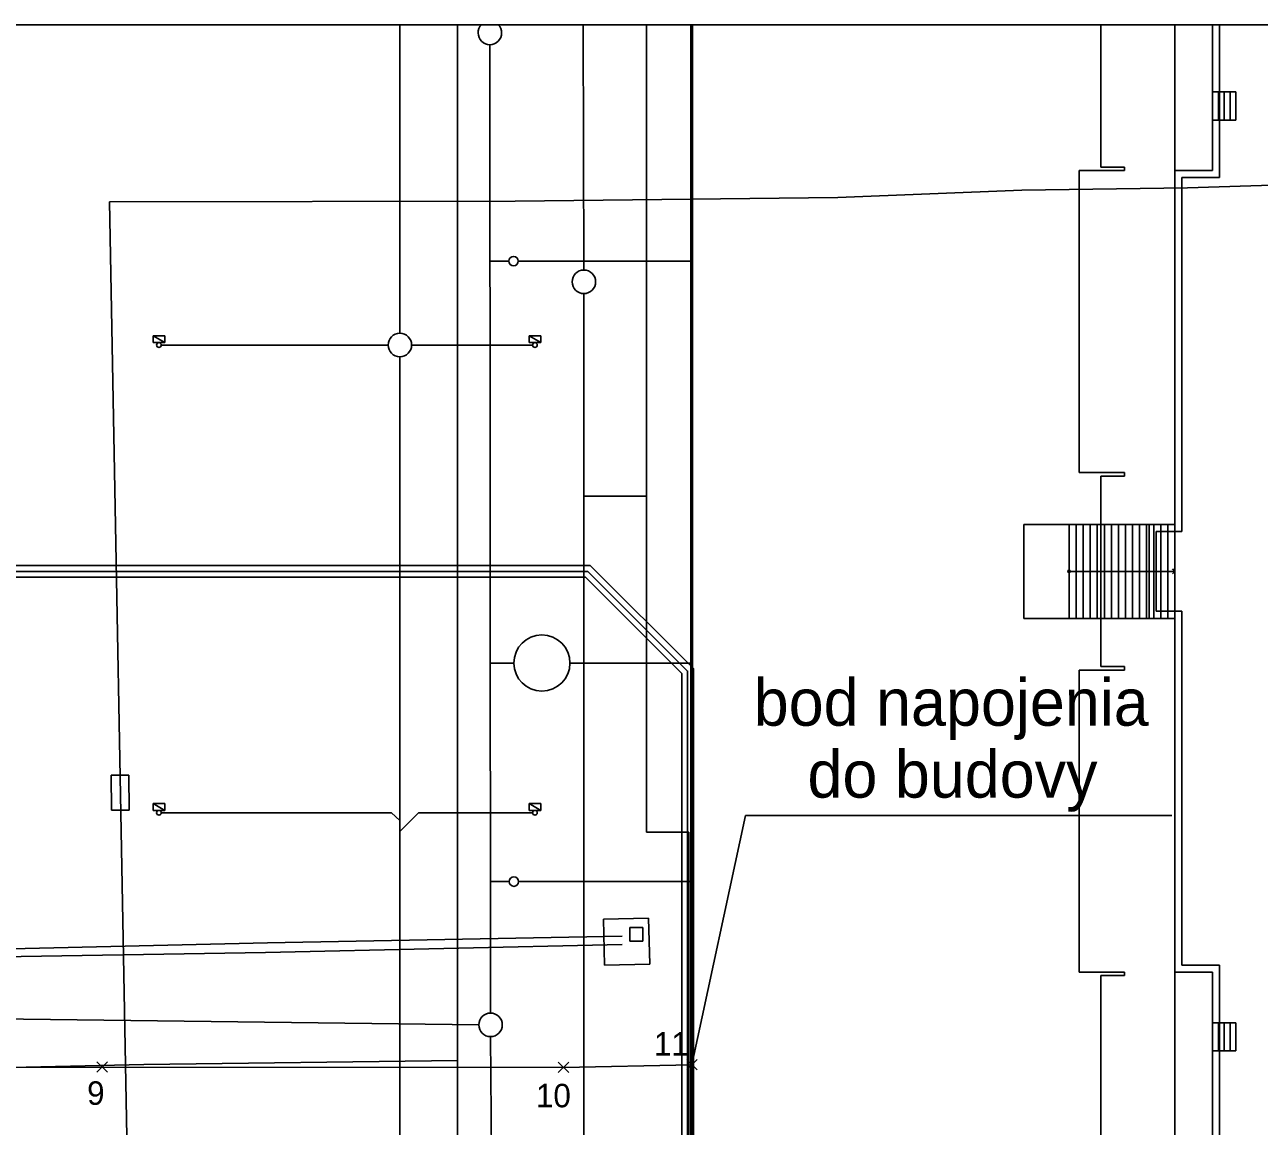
# Model space of a CAD drawing. Extents: x -264053 to -263843, y -1242290 to -1242141.
# Drawn here: x -263942.6 to -263890, y -1242188 to -1242141.1 of the extents above; entities that cross this region are included whole.
import ezdxf

# ---------------------------------------------------------------- set-up
doc = ezdxf.new("R2010")
doc.units = 0
for name, color, linetype in [('KFA_2D_JESTVUJUCE_IS_DSP', 7, 'Continuous'), ('KFA_2D_SITUACIA_DSP', 7, 'Continuous'), ('KFA_63-2_TELEKOM_PRIPOJKA', 7, 'Continuous'), ('KFA_BODY_CISLO', 7, 'Continuous'), ('KFA_BODY_SYMBOL', 7, 'Continuous'), ('POPIS', 7, 'Continuous'), ('RAM_NA_TLAC_A3_1-500', 7, 'Continuous')]:
    doc.layers.add(name, color=color, linetype=linetype)

msp = doc.modelspace()

# ---------------------------------------------------------------- linework, layer by layer
at = {"layer": 'KFA_2D_JESTVUJUCE_IS_DSP'}
for p, q in [((-263922.406, -1242141.125), (-263923.121, -1242141.125)), ((-263918.787, -1242141.125), (-263918.765, -1242151.564)), ((-263922.763, -1242141.975), (-263922.734, -1242183.174)), ((-263893.085, -1242148.072), (-263889.033, -1242147.931)), ((-263921.69, -1242148.626), (-263907.955, -1242148.477)), ((-263907.955, -1242148.477), (-263900.133, -1242148.17)), ((-263900.133, -1242148.17), (-263893.085, -1242148.072)), ((-263938.95, -1242148.666), (-263921.69, -1242148.626)), ((-263937.993, -1242200.068), (-263938.95, -1242148.666)), ((-263918.764, -1242152.564), (-263918.757, -1242196.225)), ((-263938.869, -1242173.048), (-263938.119, -1242173.046)), ((-263938.863, -1242174.548), (-263938.869, -1242173.048)), ((-263938.119, -1242173.046), (-263938.113, -1242174.546)), ((-263938.113, -1242174.546), (-263938.863, -1242174.548)), ((-263938.863, -1242174.548), (-263938.863, -1242174.548)), ((-263916.007, -1242179.139), (-263917.932, -1242179.184)), ((-263917.932, -1242179.184), (-263917.886, -1242181.133)), ((-263916.803, -1242180.116), (-263916.803, -1242179.537)), ((-263916.803, -1242179.537), (-263916.252, -1242179.537)), ((-263916.252, -1242179.537), (-263916.252, -1242180.116)), ((-263915.961, -1242181.088), (-263916.007, -1242179.139)), ((-263917.138, -1242179.908), (-263932.226, -1242180.187)), ((-263943.779, -1242180.456), (-263932.226, -1242180.187)), ((-263943.567, -1242180.776), (-263932.313, -1242180.597)), ((-263932.313, -1242180.597), (-263917.138, -1242180.263)), ((-263916.252, -1242180.116), (-263916.803, -1242180.116)), ((-263917.886, -1242181.133), (-263915.961, -1242181.088)), ((-263923.234, -1242183.668), (-263965.273, -1242183.165)), ((-263922.496, -1242219.209), (-263922.731, -1242184.174)), ((-263937.488, -1242185.363), (-263924.143, -1242185.192)), ((-263952.832, -1242185.692), (-263937.488, -1242185.363))]:
    msp.add_line(p, q, dxfattribs=at)
for centre in [(-263918.764, -1242152.064), (-263922.734, -1242183.674)]:
    msp.add_circle(centre, 0.5, dxfattribs=at)
msp.add_arc((-263922.763, -1242141.475), 0.5, 135.6071, 44.3929, dxfattribs=at)
at = {"layer": 'KFA_2D_SITUACIA_DSP'}
for p, q in [((-263926.593, -1242141.125), (-263926.593, -1242154.252)), ((-263926.593, -1242141.125), (-263926.593, -1242154.252)), ((-263924.143, -1242141.125), (-263924.143, -1242185.14)), ((-263893.618, -1242141.125), (-263916.093, -1242141.125)), ((-263916.093, -1242141.125), (-263916.093, -1242175.482)), ((-263914.218, -1242196.332), (-263914.218, -1242141.125)), ((-263896.768, -1242141.125), (-263896.768, -1242147.182)), ((-263893.618, -1242162.382), (-263893.618, -1242141.125)), ((-263843.272, -1242141.125), (-263892.018, -1242141.125)), ((-263892.018, -1242141.125), (-263892.018, -1242147.332)), ((-263892.018, -1242147.332), (-263892.018, -1242141.125)), ((-263892.018, -1242141.125), (-263843.272, -1242141.125)), ((-263843.272, -1242141.125), (-263891.718, -1242141.125)), ((-263891.718, -1242141.125), (-263891.718, -1242147.632)), ((-263892.018, -1242143.983), (-263891.018, -1242143.983)), ((-263891.768, -1242143.983), (-263891.768, -1242145.181)), ((-263891.518, -1242143.983), (-263891.518, -1242145.181)), ((-263891.268, -1242143.983), (-263891.268, -1242145.181)), ((-263891.018, -1242143.983), (-263891.018, -1242145.181)), ((-263891.018, -1242145.181), (-263892.018, -1242145.181)), ((-263895.768, -1242147.332), (-263897.693, -1242147.332)), ((-263897.693, -1242147.332), (-263897.693, -1242160.182)), ((-263896.768, -1242147.182), (-263895.768, -1242147.182)), ((-263895.768, -1242147.182), (-263895.768, -1242147.332)), ((-263892.018, -1242147.332), (-263893.618, -1242147.332)), ((-263893.618, -1242147.332), (-263893.618, -1242162.382)), ((-263893.618, -1242181.432), (-263893.618, -1242147.332)), ((-263893.618, -1242147.332), (-263892.018, -1242147.332)), ((-263891.718, -1242147.632), (-263893.318, -1242147.632)), ((-263893.318, -1242147.632), (-263893.318, -1242162.682)), ((-263921.957, -1242151.182), (-263922.757, -1242151.182)), ((-263917.093, -1242151.182), (-263921.557, -1242151.182)), ((-263914.143, -1242151.182), (-263917.093, -1242151.182)), ((-263937.093, -1242154.652), (-263937.093, -1242154.362)), ((-263937.093, -1242154.362), (-263936.593, -1242154.362)), ((-263936.593, -1242154.652), (-263937.093, -1242154.362)), ((-263936.593, -1242154.652), (-263937.093, -1242154.362)), ((-263937.093, -1242154.362), (-263937.093, -1242154.652)), ((-263936.593, -1242154.652), (-263937.093, -1242154.652)), ((-263937.093, -1242154.652), (-263936.593, -1242154.652)), ((-263936.743, -1242154.752), (-263927.093, -1242154.752)), ((-263936.593, -1242154.362), (-263936.593, -1242154.652)), ((-263920.944, -1242154.752), (-263926.093, -1242154.752)), ((-263921.093, -1242154.652), (-263921.093, -1242154.362)), ((-263921.093, -1242154.362), (-263920.593, -1242154.362)), ((-263920.593, -1242154.652), (-263921.093, -1242154.362)), ((-263920.593, -1242154.652), (-263921.093, -1242154.362)), ((-263921.093, -1242154.362), (-263921.093, -1242154.652)), ((-263920.593, -1242154.652), (-263921.093, -1242154.652)), ((-263921.093, -1242154.652), (-263920.593, -1242154.652)), ((-263920.593, -1242154.362), (-263920.593, -1242154.652)), ((-263926.593, -1242155.252), (-263926.593, -1242204.252)), ((-263897.693, -1242160.182), (-263895.768, -1242160.182)), ((-263895.768, -1242160.332), (-263896.768, -1242160.332)), ((-263896.768, -1242160.332), (-263896.768, -1242168.432)), ((-263895.768, -1242160.182), (-263895.768, -1242160.332)), ((-263916.093, -1242161.182), (-263918.763, -1242161.182)), ((-263900.043, -1242166.382), (-263900.043, -1242162.382)), ((-263900.043, -1242162.382), (-263893.618, -1242162.382)), ((-263898.118, -1242162.382), (-263898.118, -1242166.382)), ((-263897.818, -1242162.382), (-263897.818, -1242166.382)), ((-263897.518, -1242162.382), (-263897.518, -1242166.382)), ((-263897.218, -1242162.382), (-263897.218, -1242166.382)), ((-263896.918, -1242162.382), (-263896.918, -1242166.382)), ((-263896.618, -1242162.382), (-263896.618, -1242166.382)), ((-263896.318, -1242162.382), (-263896.318, -1242166.382)), ((-263896.018, -1242162.382), (-263896.018, -1242166.382)), ((-263895.718, -1242162.382), (-263895.718, -1242166.382)), ((-263895.418, -1242162.382), (-263895.418, -1242166.382)), ((-263895.118, -1242162.382), (-263895.118, -1242166.382)), ((-263894.818, -1242162.382), (-263894.818, -1242166.382)), ((-263893.618, -1242162.382), (-263894.718, -1242162.382)), ((-263894.718, -1242162.382), (-263894.718, -1242166.382)), ((-263894.518, -1242162.382), (-263894.518, -1242166.382)), ((-263893.318, -1242162.682), (-263894.418, -1242162.682)), ((-263894.418, -1242162.682), (-263894.418, -1242166.082)), ((-263894.218, -1242162.382), (-263894.218, -1242166.382)), ((-263893.918, -1242162.382), (-263893.918, -1242166.382)), ((-263893.618, -1242162.382), (-263893.618, -1242166.382)), ((-263918.489, -1242164.132), (-263946.093, -1242164.132)), ((-263893.618, -1242164.382), (-263893.721, -1242164.274)), ((-263918.593, -1242164.382), (-263946.093, -1242164.382)), ((-263918.696, -1242164.632), (-263946.093, -1242164.632)), ((-263898.118, -1242164.382), (-263893.618, -1242164.382)), ((-263893.618, -1242164.382), (-263893.721, -1242164.491)), ((-263893.618, -1242166.382), (-263900.043, -1242166.382)), ((-263894.718, -1242166.382), (-263893.618, -1242166.382)), ((-263894.418, -1242166.082), (-263893.318, -1242166.082)), ((-263893.618, -1242210.482), (-263893.618, -1242166.382)), ((-263893.618, -1242166.382), (-263893.618, -1242181.432)), ((-263893.318, -1242166.082), (-263893.318, -1242181.132)), ((-263922.745, -1242168.282), (-263921.745, -1242168.282)), ((-263914.143, -1242168.282), (-263919.355, -1242168.282)), ((-263896.768, -1242168.432), (-263895.768, -1242168.432)), ((-263895.768, -1242168.432), (-263895.768, -1242168.582)), ((-263895.768, -1242168.582), (-263897.693, -1242168.582)), ((-263897.693, -1242168.582), (-263897.693, -1242181.432)), ((-263937.093, -1242174.553), (-263937.093, -1242174.263)), ((-263937.093, -1242174.263), (-263936.593, -1242174.263)), ((-263936.593, -1242174.553), (-263937.093, -1242174.263)), ((-263936.593, -1242174.553), (-263937.093, -1242174.263)), ((-263937.093, -1242174.263), (-263937.093, -1242174.553)), ((-263936.593, -1242174.263), (-263936.593, -1242174.553)), ((-263921.093, -1242174.553), (-263921.093, -1242174.263)), ((-263921.093, -1242174.263), (-263920.593, -1242174.263)), ((-263920.593, -1242174.553), (-263921.093, -1242174.263)), ((-263920.593, -1242174.553), (-263921.093, -1242174.263)), ((-263921.093, -1242174.263), (-263921.093, -1242174.553)), ((-263920.593, -1242174.263), (-263920.593, -1242174.553)), ((-263936.593, -1242174.553), (-263937.093, -1242174.553)), ((-263937.093, -1242174.553), (-263936.593, -1242174.553)), ((-263936.743, -1242174.653), (-263926.953, -1242174.653)), ((-263926.953, -1242174.653), (-263926.593, -1242174.978)), ((-263925.798, -1242174.653), (-263926.593, -1242175.448)), ((-263920.944, -1242174.653), (-263925.798, -1242174.653)), ((-263920.593, -1242174.553), (-263921.093, -1242174.553)), ((-263921.093, -1242174.553), (-263920.593, -1242174.553)), ((-263916.093, -1242175.482), (-263914.293, -1242175.482)), ((-263914.293, -1242175.482), (-263914.293, -1242210.482)), ((-263921.938, -1242177.582), (-263922.738, -1242177.582)), ((-263915.293, -1242177.582), (-263921.538, -1242177.582)), ((-263914.143, -1242177.582), (-263915.293, -1242177.582)), ((-263897.693, -1242181.432), (-263895.768, -1242181.432)), ((-263895.768, -1242181.582), (-263896.768, -1242181.582)), ((-263896.768, -1242181.582), (-263896.768, -1242203.332)), ((-263895.768, -1242181.432), (-263895.768, -1242181.582)), ((-263893.618, -1242181.432), (-263892.018, -1242181.432)), ((-263892.018, -1242181.432), (-263893.618, -1242181.432)), ((-263893.318, -1242181.132), (-263891.718, -1242181.132)), ((-263892.018, -1242181.432), (-263892.018, -1242219.209)), ((-263892.018, -1242219.209), (-263892.018, -1242181.432)), ((-263891.718, -1242181.132), (-263891.718, -1242219.209)), ((-263892.018, -1242183.583), (-263891.018, -1242183.583)), ((-263891.768, -1242183.583), (-263891.768, -1242184.781)), ((-263891.518, -1242183.583), (-263891.518, -1242184.781)), ((-263891.268, -1242183.583), (-263891.268, -1242184.781)), ((-263891.018, -1242183.583), (-263891.018, -1242184.781)), ((-263891.018, -1242184.781), (-263892.018, -1242184.781)), ((-263924.143, -1242185.14), (-263924.143, -1242219.209))]:
    msp.add_line(p, q, dxfattribs=at)
for points in [[(-263909.043, -1242219.209), (-263909.043, -1242196.333), (-263914.143, -1242196.333), (-263914.143, -1242141.125)], [(-263918.489, -1242164.132), (-263914.1, -1242168.521), (-263914.1, -1242199.486), (-263910.004, -1242203.582), (-263891.768, -1242203.582)], [(-263918.696, -1242164.632), (-263914.6, -1242168.728), (-263914.6, -1242199.693), (-263910.211, -1242204.082), (-263891.768, -1242204.082)], [(-263918.593, -1242164.382), (-263914.35, -1242168.625), (-263914.35, -1242199.59), (-263910.108, -1242203.832), (-263891.768, -1242203.832)]]:
    msp.add_lwpolyline(points, dxfattribs=at)
for centre, radius in [((-263921.757, -1242151.182), 0.2), ((-263926.593, -1242154.752), 0.5), ((-263936.843, -1242154.752), 0.1), ((-263920.844, -1242154.752), 0.1), ((-263898.118, -1242164.382), 0.05), ((-263920.55, -1242168.282), 1.195), ((-263936.843, -1242174.653), 0.1), ((-263920.844, -1242174.653), 0.1), ((-263921.738, -1242177.582), 0.2)]:
    msp.add_circle(centre, radius, dxfattribs=at)
at = {"layer": 'KFA_63-2_TELEKOM_PRIPOJKA'}
msp.add_lwpolyline([(-264029.881, -1242182.077), (-264029.905, -1242185.793), (-264029.004, -1242186.266), (-264023.98, -1242186.128), (-264003.402, -1242186.128), (-263982.858, -1242186.12), (-263966.19, -1242185.767), (-263953.396, -1242185.506), (-263939.258, -1242185.468), (-263919.631, -1242185.484), (-263914.168, -1242185.372)], dxfattribs=at)
at = {"layer": 'KFA_BODY_SYMBOL'}
for p, q in [((-263939.479, -1242185.689), (-263939.037, -1242185.247)), ((-263939.037, -1242185.689), (-263939.479, -1242185.247)), ((-263919.852, -1242185.705), (-263919.41, -1242185.263)), ((-263919.41, -1242185.705), (-263919.852, -1242185.263)), ((-263914.389, -1242185.593), (-263913.947, -1242185.151)), ((-263913.947, -1242185.593), (-263914.389, -1242185.151))]:
    msp.add_line(p, q, dxfattribs=at)
at = {"layer": 'POPIS'}
for p in [(-263914.168, -1242185.372), (-263893.745, -1242174.764)]:
    msp.add_line(p, (-263911.886, -1242174.764), dxfattribs=at)
at = {"layer": 'RAM_NA_TLAC_A3_1-500'}
msp.add_lwpolyline([(-264053.272, -1242141.125), (-263843.272, -1242141.125), (-263843.272, -1242289.625), (-264053.272, -1242289.625)], close=True, dxfattribs=at)

# ---------------------------------------------------------------- texts
at = {"layer": 'KFA_BODY_CISLO'}
for s, p in [('11', (-263915.784, -1242184.982)), ('9', (-263939.9, -1242187.077)), ('10', (-263920.805, -1242187.183))]:
    msp.add_text(s, height=1, dxfattribs=at).set_placement(p)
at = {"layer": 'POPIS'}
for s, p in [('bod napojenia', (-263911.537, -1242170.949)), ('do budovy', (-263909.25, -1242174.009))]:
    msp.add_text(s, height=2, dxfattribs=at).set_placement(p)

doc.saveas('drawing.dxf')
